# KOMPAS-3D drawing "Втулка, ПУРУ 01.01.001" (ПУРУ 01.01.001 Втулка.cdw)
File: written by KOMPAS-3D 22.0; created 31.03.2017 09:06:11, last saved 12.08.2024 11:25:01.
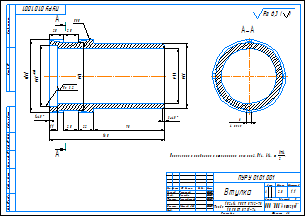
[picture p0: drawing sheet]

Sheet 1: A3, landscape

Document properties: Автор: cons; Полное имя файла: D:\Вован\Антиград\Град\12.02.2025\ПУРУ 01.00.000 Стойка\ПУРУ 01.01.000 Ось\Чертежи\ПУРУ 01.01.001 Втулка.cdw; Масса: 2.756154; Знак неуказанной шероховатости: 4; Параметр неуказанной шероховатости: Ra 6,3

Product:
- Body: Тело 1
    Материал: Труба$d102x14 ГОСТ 8732-78;10 ГОСТ 8731-74$ (density 7856 kg/m3)
- Part/product: Втулка  | designation ПУРУ 01.01.001
    Материал: Труба$d102x14 ГОСТ 8732-78;10 ГОСТ 8731-74$ (density 7856 kg/m3)
    Масса: 2.756154
    Раздел спецификации: Детали
    Форматы листов документа: A3
    source file: ..\ПУРУ 01.01.001 Втулка.m3d, ПУРУ 01.01.001 Втулка.cdw
- Part/product: (unnamed)  | designation 1
- Part/product: (unnamed)  | designation 2
- Part/product: (unnamed)  | designation 3

Table, sheet 1:
  0;Material:VDE12371B5FDD453AAD3A0896F0FE5778;Sortament:VACA86AD6B524487FA06521D22EE88F1C^SortamentEx:V7C47B5BC21454BBF9A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
Title block, sheet 2: Наименование: Втулка; designation: ПУРУ 01.01.001; Материал: Труба 102x14 ГОСТ 8732-78 10 ГОСТ 8731-74; Масса: 2,8; sheet number: 1; organisation: ООО "НПЦ"Антиград"; Форматы листов документа: A3; Литера: А; stored path: D:\РУ 00.00.000 Установка противоградовая ручная\РУ 01.00.000 Стойка\РУ 01.01.000 Ось\Чертежи\РУ 01.01.001 Втулка.cdw; Разработал: Грицунов; Проверил: Налоева; Т. контр.: Семеновский; Н. контр.: Абшаев А.М.; Разработал, date: 03.04.2017; Проверил, date: 03.04.2017; Т. контр., date: 03.04.2017; Н. контр., date: 03.04.2017

Views: Вид 1, Местный разрез 1, Сзади, Разрез А-А
Referenced files in D:\Град\ПУРУ 00.00.000 Установка пусковая ручная Элия-Р\ПУРУ 01.00.000 Стойка\ПУРУ 01.01.000 Ось\: ПУРУ 01.01.001 Втулка.m3d
Referenced files in D:\Вован\Антиград\Град\ПУРУ 00.00.000 Установка пусковая ручная Элия-Р\ПУРУ 01.00.000 Стойка\ПУРУ 01.01.000 Ось\: ПУРУ 01.01.001 Втулка.m3d
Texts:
  Ra 3,2
  Ra 6,3
  Ra 6,3 ( )
  ПУРУ 01.01.001 Втулка
Dimensions and other numbers on the sheet: 101; 85; 77; 90; 11; 3; 98; 22; 20; 160; 1; 50; 94; 5; 6; 4 паза; 1:1; 2,8; 03.04.2017

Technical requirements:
  Неуказанные предельные отклонения размеров: H14, h14,    IT14 2 .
